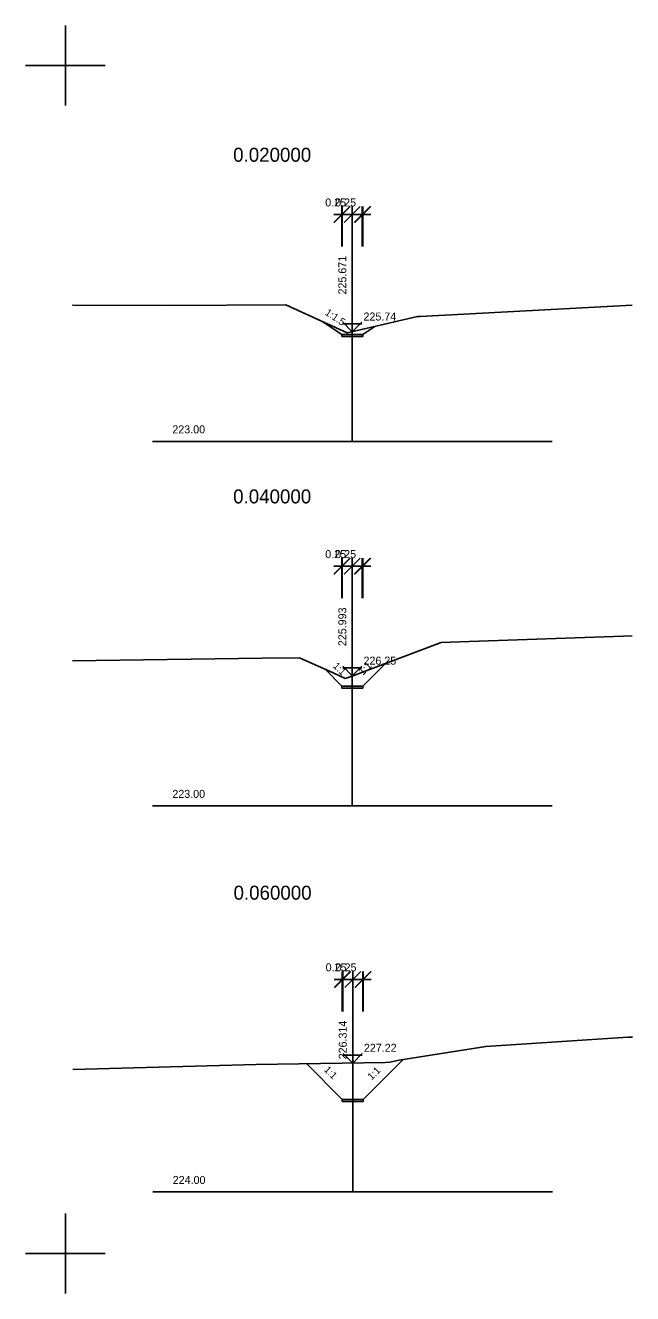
# Model space of a CAD drawing. Extents: x -10 to 433, y -10 to 307.
# Drawn here: x -10 to 141.9, y -10 to 307 of the extents above; entities that cross this region are included whole.
import ezdxf

# ---------------------------------------------------------------- set-up
doc = ezdxf.new("R2010")
doc.units = 0
doc.layers.add('FORMATY', color=7, linetype='Continuous')
doc.layers.add('WORKING_LAYER', color=7, linetype='Continuous')

# ---------------------------------------------------------------- blocks, each defined once
blk = doc.blocks.new('Cross2')
at = {"layer": 'WORKING_LAYER'}
for p, q in [((-0.6, 58.71265), (-4.6, 54.71265)), ((-0.5, 58.71265), (-4.5, 54.71265)), ((-2.6, 56.71265), (-0.6, 58.71265)), ((-2.6, 58.71265), (-2.6, 56.71265)), ((-2.6, 48.71265), (-2.6, 58.71265)), ((-2.5, 58.71265), (-2.5, 48.71265)), ((-2.5, 56.71265), (-2.5, 58.71265)), ((-2.5, 56.71265), (-0.5, 58.71265)), ((2, 58.71265), (-2, 54.71265)), ((2, 58.71265), (-2, 54.71265)), ((0, 58.71265), (0, 48.71265)), ((0, 56.71265), (0, 58.71265)), ((0, 56.71265), (2, 58.71265)), ((0, 58.71265), (0, 48.71265)), ((0, 56.71265), (0, 58.71265)), ((0, 56.71265), (2, 58.71265)), ((4.5, 58.71265), (0.5, 54.71265)), ((4.6, 58.71265), (0.6, 54.71265)), ((2.5, 58.71265), (2.5, 48.71265)), ((2.5, 56.71265), (2.5, 58.71265)), ((2.5, 56.71265), (4.5, 58.71265)), ((2.6, 58.71265), (2.6, 48.71265)), ((2.6, 56.71265), (2.6, 58.71265)), ((2.6, 56.71265), (4.6, 58.71265)), ((-4.6, 56.71265), (-0.5, 56.71265)), ((-2.6, 56.71265), (-4.6, 56.71265)), ((-4.6, 54.71265), (-2.6, 56.71265)), ((-4.5, 54.71265), (-2.5, 56.71265)), ((-2.5, 56.71265), (2, 56.71265)), ((-0.5, 56.71265), (-2.5, 56.71265)), ((-2, 54.71265), (0, 56.71265)), ((-2, 54.71265), (0, 56.71265)), ((0, 56.71265), (4.5, 56.71265)), ((2, 56.71265), (0, 56.71265)), ((0, 56.71265), (2, 56.71265)), ((2, 56.71265), (0, 56.71265)), ((0.5, 54.71265), (2.5, 56.71265)), ((0.6, 54.71265), (2.6, 56.71265)), ((2.5, 56.71265), (4.6, 56.71265)), ((4.5, 56.71265), (2.5, 56.71265)), ((4.6, 56.71265), (2.6, 56.71265)), ((0, 0), (0, 49.88937)), ((-70, 34.04085), (-69.88, 34.01993)), ((-69.88, 34.01993), (-46.24, 33.97995)), ((-46.24, 33.97995), (-16.6, 34.10004)), ((-16.6, 34.10004), (-12.66, 32.29996)), ((-12.66, 32.29996), (-1.26, 27.10999)), ((16.96, 31.19995), (70, 34.08463)), ((-7.36518, 29.88937), (-2.61, 26.71265)), ((-2.61, 26.71265), (-7.36518, 29.88937)), ((0, 27.40707), (-2.4, 29.80708)), ((-2.4, 29.40707), (2.4, 29.40707)), ((0, 27.40707), (2.4, 29.80708)), ((2.61, 26.71265), (5.63583, 28.73657)), ((2.61, 26.71265), (5.63583, 28.73657)), ((3.364, 28.20007), (16.28, 31.25)), ((16.28, 31.25), (16.96, 31.19995)), ((-2.61, 26.71265), (-2.6, 26.21262)), ((-2.5, 26.71265), (-2.6, 26.71265)), ((-2.6, 26.21262), (-2.5, 26.21262)), ((0, 26.71265), (-2.5, 26.71265)), ((-2.5, 26.21262), (0, 26.21262)), ((-1.26, 27.10999), (3.364, 28.20007)), ((0, 26.71265), (2.5, 26.71265)), ((0, 26.21262), (2.5, 26.21262)), ((0, 26.21262), (0, 26.21262)), ((2.5, 26.71265), (2.6, 26.71265)), ((2.5, 26.21262), (2.6, 26.21262)), ((2.6, 26.21262), (2.61, 26.71265)), ((-50, 0), (50, 0))]:
    blk.add_line(p, q, dxfattribs=at)
for s, height, p in [('    0.020000', 3.5, (-35, 69.88937)), ('  0.25', 2, (-8.25, 58.71265)), ('  0.25', 2, (-5.75, 58.71265)), ('225.74', 2, (2.8, 30.20707)), ('223.00', 2, (-45, 2))]:
    blk.add_text(s, height=height, dxfattribs=at).set_placement(p)
for s, height, rotation, p in [('225.671', 2, 90, (-1.5, 36.71265)), ('1:1.5', 1.8, 326.25486, (-6.98116, 31.79749))]:
    blk.add_text(s, height=height, rotation=rotation, dxfattribs=at).set_placement(p)
blk = doc.blocks.new('Cross3')
at = {"layer": 'WORKING_LAYER'}
for p, q in [((-0.6, 61.92538), (-4.6, 57.92538)), ((-0.5, 61.92538), (-4.5, 57.92538)), ((-2.6, 59.92538), (-0.6, 61.92538)), ((-2.6, 61.92538), (-2.6, 59.92538)), ((-2.6, 51.92538), (-2.6, 61.92538)), ((-2.5, 61.92538), (-2.5, 51.92538)), ((-2.5, 59.92538), (-2.5, 61.92538)), ((-2.5, 59.92538), (-0.5, 61.92538)), ((2, 61.92538), (-2, 57.92538)), ((2, 61.92538), (-2, 57.92538)), ((0, 61.92538), (0, 51.92538)), ((0, 59.92538), (0, 61.92538)), ((0, 59.92538), (2, 61.92538)), ((0, 61.92538), (0, 51.92538)), ((0, 59.92538), (0, 61.92538)), ((0, 59.92538), (2, 61.92538)), ((4.5, 61.92538), (0.5, 57.92538)), ((4.6, 61.92538), (0.6, 57.92538)), ((2.5, 61.92538), (2.5, 51.92538)), ((2.5, 59.92538), (2.5, 61.92538)), ((2.5, 59.92538), (4.5, 61.92538)), ((2.6, 61.92538), (2.6, 51.92538)), ((2.6, 59.92538), (2.6, 61.92538)), ((2.6, 59.92538), (4.6, 61.92538)), ((-4.6, 59.92538), (-0.5, 59.92538)), ((-2.6, 59.92538), (-4.6, 59.92538)), ((-4.6, 57.92538), (-2.6, 59.92538)), ((-4.5, 57.92538), (-2.5, 59.92538)), ((-2.5, 59.92538), (2, 59.92538)), ((-0.5, 59.92538), (-2.5, 59.92538)), ((-2, 57.92538), (0, 59.92538)), ((-2, 57.92538), (0, 59.92538)), ((0, 59.92538), (4.5, 59.92538)), ((2, 59.92538), (0, 59.92538)), ((0, 59.92538), (2, 59.92538)), ((2, 59.92538), (0, 59.92538)), ((0.5, 57.92538), (2.5, 59.92538)), ((0.6, 57.92538), (2.6, 59.92538)), ((2.5, 59.92538), (4.6, 59.92538)), ((4.5, 59.92538), (2.5, 59.92538)), ((4.6, 59.92538), (2.6, 59.92538)), ((0, 0), (0, 55.60699)), ((29.24, 41.08994), (67.8, 42.40005)), ((67.8, 42.40005), (70, 42.51287)), ((-0.5551, 32.29004), (22.25, 40.85007)), ((22.25, 40.85007), (29.24, 41.08994)), ((-70, 36.22322), (-22.51, 36.95007)), ((-22.51, 36.95007), (-13.23, 37.03003)), ((-13.23, 37.03003), (-4.774, 33.22006)), ((0, 32.49847), (-2.4, 34.89848)), ((0, 32.49847), (2.4, 34.89848)), ((2.61, 29.92538), (8.28162, 35.60699)), ((2.61, 29.92538), (8.28162, 35.60699)), ((-6.81369, 34.1391), (-2.61, 29.92538)), ((-2.61, 29.92538), (-6.81369, 34.1391)), ((-4.774, 33.22006), (-1.746, 31.86005)), ((-2.4, 34.49847), (2.4, 34.49847)), ((-1.746, 31.86005), (-0.5551, 32.29004)), ((-2.61, 29.92538), (-2.6, 29.42535)), ((-2.5, 29.92538), (-2.6, 29.92538)), ((-2.6, 29.42535), (-2.5, 29.42535)), ((0, 29.92538), (-2.5, 29.92538)), ((-2.5, 29.42535), (0, 29.42535)), ((0, 29.92538), (2.5, 29.92538)), ((0, 29.42535), (2.5, 29.42535)), ((0, 29.42535), (0, 29.42535)), ((2.5, 29.92538), (2.6, 29.92538)), ((2.5, 29.42535), (2.6, 29.42535)), ((2.6, 29.42535), (2.61, 29.92538)), ((-50, 0), (50, 0))]:
    blk.add_line(p, q, dxfattribs=at)
for s, height, p in [('    0.040000', 3.5, (-35, 75.60699)), ('  0.25', 2, (-8.25, 61.92538)), ('  0.25', 2, (-5.75, 61.92538)), ('226.25', 2, (2.8, 35.29847)), ('223.00', 2, (-45, 2))]:
    blk.add_text(s, height=height, dxfattribs=at).set_placement(p)
for s, height, rotation, p in [('225.993', 2, 90, (-1.5, 39.92538)), ('1:1', 1.8, 314.93174, (-4.96307, 34.83261)), ('1:1', 1.8, 45.05045, (2.64589, 32.50916))]:
    blk.add_text(s, height=height, rotation=rotation, dxfattribs=at).set_placement(p)
blk = doc.blocks.new('Cross4')
at = {"layer": 'WORKING_LAYER'}
for p, q in [((-0.6, 55.13797), (-4.6, 51.13797)), ((-0.5, 55.13797), (-4.5, 51.13797)), ((-2.6, 53.13797), (-0.6, 55.13797)), ((-2.6, 55.13797), (-2.6, 53.13797)), ((-2.6, 45.13797), (-2.6, 55.13797)), ((-2.5, 55.13797), (-2.5, 45.13797)), ((-2.5, 53.13797), (-2.5, 55.13797)), ((-2.5, 53.13797), (-0.5, 55.13797)), ((2, 55.13797), (-2, 51.13797)), ((2, 55.13797), (-2, 51.13797)), ((0, 55.13797), (0, 45.13797)), ((0, 53.13797), (0, 55.13797)), ((0, 53.13797), (2, 55.13797)), ((0, 55.13797), (0, 45.13797)), ((0, 53.13797), (0, 55.13797)), ((0, 53.13797), (2, 55.13797)), ((4.5, 55.13797), (0.5, 51.13797)), ((4.6, 55.13797), (0.6, 51.13797)), ((2.5, 55.13797), (2.5, 45.13797)), ((2.5, 53.13797), (2.5, 55.13797)), ((2.5, 53.13797), (4.5, 55.13797)), ((2.6, 55.13797), (2.6, 45.13797)), ((2.6, 53.13797), (2.6, 55.13797)), ((2.6, 53.13797), (4.6, 55.13797)), ((-4.6, 53.13797), (-0.5, 53.13797)), ((-2.6, 53.13797), (-4.6, 53.13797)), ((-4.6, 51.13797), (-2.6, 53.13797)), ((-4.5, 51.13797), (-2.5, 53.13797)), ((-2.5, 53.13797), (2, 53.13797)), ((-0.5, 53.13797), (-2.5, 53.13797)), ((-2, 51.13797), (0, 53.13797)), ((-2, 51.13797), (0, 53.13797)), ((0, 53.13797), (4.5, 53.13797)), ((2, 53.13797), (0, 53.13797)), ((0, 53.13797), (2, 53.13797)), ((2, 53.13797), (0, 53.13797)), ((0, 0), (0, 53.04138)), ((0.5, 51.13797), (2.5, 53.13797)), ((0.6, 51.13797), (2.6, 53.13797)), ((2.5, 53.13797), (4.6, 53.13797)), ((4.5, 53.13797), (2.5, 53.13797)), ((4.6, 53.13797), (2.6, 53.13797)), ((33.29, 36.36993), (68.79, 38.67996)), ((68.79, 38.67996), (70, 38.70976)), ((11.62, 32.89993), (33.29, 36.36993)), ((-70, 30.57755), (-24.18, 31.82999)), ((-24.18, 31.82999), (8.088, 32.35001)), ((-11.49644, 32.03445), (-2.61, 23.13797)), ((-2.61, 23.13797), (-11.49644, 32.03445)), ((0, 32.2197), (-2.4, 34.6197)), ((-2.4, 34.2197), (2.4, 34.2197)), ((0, 32.2197), (2.4, 34.6197)), ((2.61, 23.13797), (12.50343, 33.04138)), ((2.61, 23.13797), (12.50343, 33.04138)), ((8.088, 32.35001), (9.277, 32.40005)), ((9.277, 32.40005), (11.62, 32.89993)), ((-2.61, 23.13797), (-2.6, 22.63794)), ((-2.5, 23.13797), (-2.6, 23.13797)), ((-2.6, 22.63794), (-2.5, 22.63794)), ((0, 23.13797), (-2.5, 23.13797)), ((-2.5, 22.63794), (0, 22.63794)), ((0, 23.13797), (2.5, 23.13797)), ((0, 22.63794), (2.5, 22.63794)), ((0, 22.63794), (0, 22.63794)), ((2.5, 23.13797), (2.6, 23.13797)), ((2.5, 22.63794), (2.6, 22.63794)), ((2.6, 22.63794), (2.61, 23.13797)), ((-50, 0), (50, 0))]:
    blk.add_line(p, q, dxfattribs=at)
for s, height, p in [('    0.060000', 3.5, (-35, 73.04138)), ('  0.25', 2, (-8.25, 55.13797)), ('  0.25', 2, (-5.75, 55.13797)), ('227.22', 2, (2.8, 35.0197)), ('224.00', 2, (-45, 2))]:
    blk.add_text(s, height=height, dxfattribs=at).set_placement(p)
for s, height, rotation, p in [('226.314', 2, 90, (-1.5, 33.13797)), ('1:1', 1.8, 314.96764, (-7.3062, 30.38651)), ('1:1', 1.8, 45.0289, (4.75671, 27.83371))]:
    blk.add_text(s, height=height, rotation=rotation, dxfattribs=at).set_placement(p)

msp = doc.modelspace()

# ---------------------------------------------------------------- linework, layer by layer
at = {"layer": 'FORMATY'}
for p, q in [((0, 307), (0, 287)), ((-10, 297), (10, 297)), ((0, 10), (0, -10)), ((-10, 0), (10, 0))]:
    msp.add_line(p, q, dxfattribs=at)

# ---------------------------------------------------------------- block references
at = {"layer": 'WORKING_LAYER'}
for name, p in [('Cross2', (71.76, 203.02)), ('Cross3', (71.76, 111.91)), ('Cross4', (71.86, 15.42))]:
    msp.add_blockref(name, p, dxfattribs=at)

doc.saveas('drawing.dxf')
